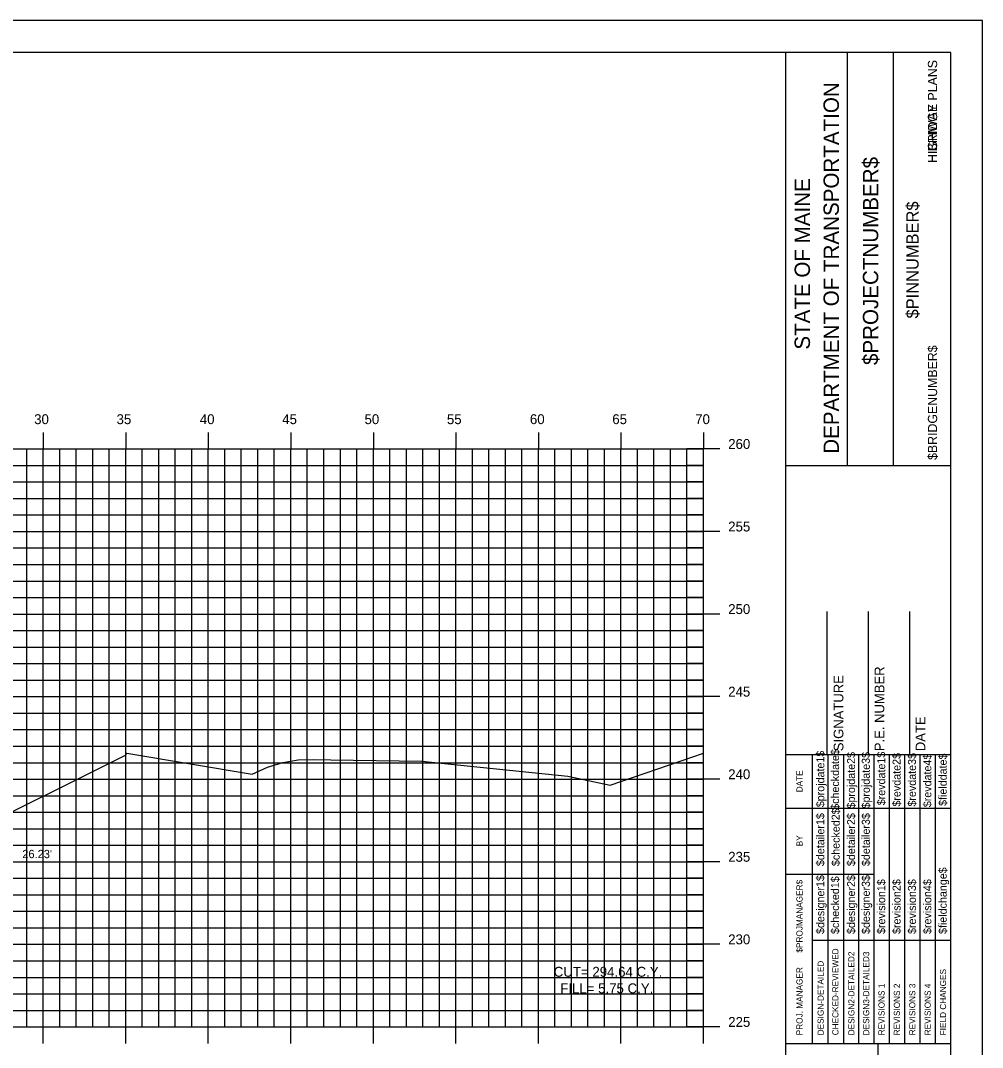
# Model space of a CAD drawing. Extents: x 1170543 to 1177585, y 609599 to 610623.
# Drawn here: x 1173611.6 to 1173669.9, y 609646.6 to 609708.8 of the extents above; entities that cross this region are included whole.
import ezdxf

# ---------------------------------------------------------------- set-up
doc = ezdxf.new("R2010")
doc.units = 0
for name, color, linetype in [('ANNOTATION', 7, 'Continuous'), ('BORDER', 7, 'Continuous'), ('BRIDGE_TITLE', 7, 'Continuous'), ('D_Roadway_Centerline_Text', 7, 'Continuous'), ('H_V ANNOTATION', 7, 'Continuous'), ('HIGHWAY_TITLE', 7, 'Continuous'), ('MAJOR', 7, 'Continuous'), ('MINOR', 7, 'Continuous'), ('PLOT BOUNDARY', 7, 'Continuous'), ('S_Roadway_Centerline', 7, 'Continuous')]:
    doc.layers.add(name, color=color, linetype=linetype)

msp = doc.modelspace()

# ---------------------------------------------------------------- linework, layer by layer
at = {"layer": 'BORDER'}
for p, q in [((1173668.017, 609706.872), (1173508.017, 609706.872)), ((1173658.017, 609601.875), (1173658.017, 609706.875)), ((1173661.746, 609681.869), (1173661.746, 609706.869)), ((1173664.541, 609681.869), (1173664.541, 609706.869)), ((1173668.017, 609601.875), (1173668.017, 609706.875)), ((1173658.018, 609681.866), (1173668.017, 609681.866)), ((1173660.517, 609664.375), (1173660.517, 609673.023)), ((1173663.017, 609664.375), (1173663.017, 609673.023)), ((1173665.517, 609664.375), (1173665.517, 609673.023)), ((1173658.017, 609664.375), (1173668.017, 609664.375)), ((1173658.017, 609646.875), (1173668.017, 609646.875)), ((1173663.608, 609611.875), (1173663.608, 609646.875))]:
    msp.add_line(p, q, dxfattribs=at)
for points in [[(1173659.632, 609661.125), (1173659.632, 609664.375)], [(1173660.565, 609646.878), (1173660.565, 609664.375)], [(1173661.497, 609664.375), (1173661.497, 609646.878)], [(1173662.428, 609646.878), (1173662.428, 609664.375)], [(1173663.36, 609646.878), (1173663.36, 609664.375)], [(1173664.292, 609646.878), (1173664.292, 609664.375)], [(1173665.223, 609646.878), (1173665.223, 609664.375)], [(1173666.155, 609646.878), (1173666.155, 609664.375)], [(1173667.087, 609646.878), (1173667.087, 609664.375)], [(1173659.633, 609646.878), (1173659.633, 609663.669)], [(1173658.017, 609661.125), (1173668.017, 609661.125)], [(1173658.017, 609657.125), (1173659.633, 609657.125)], [(1173659.632, 609657.125), (1173663.359, 609657.125)], [(1173659.632, 609653.125), (1173668.017, 609653.125)]]:
    msp.add_lwpolyline(points, dxfattribs=at)
at = {"layer": 'MAJOR'}
for p, q in [((1173613.017, 609683.874), (1173613.017, 609682.872)), ((1173618.017, 609683.874), (1173618.017, 609682.872)), ((1173623.017, 609683.874), (1173623.017, 609682.872)), ((1173628.017, 609683.874), (1173628.017, 609682.872)), ((1173633.017, 609683.874), (1173633.017, 609682.872)), ((1173638.017, 609683.874), (1173638.017, 609682.872)), ((1173643.017, 609683.874), (1173643.017, 609682.872)), ((1173648.017, 609683.874), (1173648.017, 609682.872)), ((1173653.017, 609683.874), (1173653.017, 609682.872)), ((1173513.017, 609682.872), (1173653.017, 609682.872)), ((1173513.017, 609682.872), (1173653.017, 609682.872)), ((1173613.017, 609647.872), (1173613.017, 609682.872)), ((1173618.017, 609647.872), (1173618.017, 609682.872)), ((1173623.017, 609647.872), (1173623.017, 609682.872)), ((1173628.017, 609647.872), (1173628.017, 609682.872)), ((1173633.017, 609647.872), (1173633.017, 609682.872)), ((1173638.017, 609647.872), (1173638.017, 609682.872)), ((1173643.017, 609647.872), (1173643.017, 609682.872)), ((1173648.017, 609647.872), (1173648.017, 609682.872)), ((1173654.019, 609682.872), (1173652.015, 609682.872)), ((1173653.017, 609647.872), (1173653.017, 609682.872)), ((1173653.017, 609647.872), (1173653.017, 609682.872)), ((1173513.017, 609677.872), (1173653.017, 609677.872)), ((1173654.019, 609677.872), (1173652.015, 609677.872)), ((1173513.017, 609672.872), (1173653.017, 609672.872)), ((1173654.019, 609672.872), (1173652.015, 609672.872)), ((1173513.017, 609667.872), (1173653.017, 609667.872)), ((1173654.019, 609667.872), (1173652.015, 609667.872)), ((1173513.017, 609662.872), (1173653.017, 609662.872)), ((1173654.019, 609662.872), (1173652.015, 609662.872)), ((1173513.017, 609657.872), (1173653.017, 609657.872)), ((1173654.019, 609657.872), (1173652.015, 609657.872)), ((1173513.017, 609652.872), (1173653.017, 609652.872)), ((1173654.019, 609652.872), (1173652.015, 609652.872)), ((1173513.017, 609647.872), (1173653.017, 609647.872)), ((1173513.017, 609647.872), (1173653.017, 609647.872)), ((1173613.017, 609646.87), (1173613.017, 609647.872)), ((1173618.017, 609646.87), (1173618.017, 609647.872)), ((1173623.017, 609646.87), (1173623.017, 609647.872)), ((1173628.017, 609646.87), (1173628.017, 609647.872)), ((1173633.017, 609646.87), (1173633.017, 609647.872)), ((1173638.017, 609646.87), (1173638.017, 609647.872)), ((1173643.017, 609646.87), (1173643.017, 609647.872)), ((1173648.017, 609646.87), (1173648.017, 609647.872)), ((1173654.019, 609647.872), (1173652.015, 609647.872)), ((1173653.017, 609646.87), (1173653.017, 609647.872))]:
    msp.add_line(p, q, dxfattribs=at)
at = {"layer": 'MINOR'}
for p, q in [((1173612.017, 609647.872), (1173612.017, 609682.872)), ((1173614.017, 609647.872), (1173614.017, 609682.872)), ((1173615.017, 609647.872), (1173615.017, 609682.872)), ((1173616.017, 609647.872), (1173616.017, 609682.872)), ((1173617.017, 609647.872), (1173617.017, 609682.872)), ((1173619.017, 609647.872), (1173619.017, 609682.872)), ((1173620.017, 609647.872), (1173620.017, 609682.872)), ((1173621.017, 609647.872), (1173621.017, 609682.872)), ((1173622.017, 609647.872), (1173622.017, 609682.872)), ((1173624.017, 609647.872), (1173624.017, 609682.872)), ((1173625.017, 609647.872), (1173625.017, 609682.872)), ((1173626.017, 609647.872), (1173626.017, 609682.872)), ((1173627.017, 609647.872), (1173627.017, 609682.872)), ((1173629.017, 609647.872), (1173629.017, 609682.872)), ((1173630.017, 609647.872), (1173630.017, 609682.872)), ((1173631.017, 609647.872), (1173631.017, 609682.872)), ((1173632.017, 609647.872), (1173632.017, 609682.872)), ((1173634.017, 609647.872), (1173634.017, 609682.872)), ((1173635.017, 609647.872), (1173635.017, 609682.872)), ((1173636.017, 609647.872), (1173636.017, 609682.872)), ((1173637.017, 609647.872), (1173637.017, 609682.872)), ((1173639.017, 609647.872), (1173639.017, 609682.872)), ((1173640.017, 609647.872), (1173640.017, 609682.872)), ((1173641.017, 609647.872), (1173641.017, 609682.872)), ((1173642.017, 609647.872), (1173642.017, 609682.872)), ((1173644.017, 609647.872), (1173644.017, 609682.872)), ((1173645.017, 609647.872), (1173645.017, 609682.872)), ((1173646.017, 609647.872), (1173646.017, 609682.872)), ((1173647.017, 609647.872), (1173647.017, 609682.872)), ((1173649.017, 609647.872), (1173649.017, 609682.872)), ((1173650.017, 609647.872), (1173650.017, 609682.872)), ((1173651.017, 609647.872), (1173651.017, 609682.872)), ((1173652.017, 609647.872), (1173652.017, 609682.872)), ((1173513.017, 609681.872), (1173653.017, 609681.872)), ((1173653.017, 609681.872), (1173652.015, 609681.872)), ((1173513.017, 609680.872), (1173653.017, 609680.872)), ((1173653.017, 609680.872), (1173652.015, 609680.872)), ((1173513.017, 609679.872), (1173653.017, 609679.872)), ((1173653.017, 609679.872), (1173652.015, 609679.872)), ((1173513.017, 609678.872), (1173653.017, 609678.872)), ((1173653.017, 609678.872), (1173652.015, 609678.872)), ((1173513.017, 609676.872), (1173653.017, 609676.872)), ((1173653.017, 609676.872), (1173652.015, 609676.872)), ((1173513.017, 609675.872), (1173653.017, 609675.872)), ((1173653.017, 609675.872), (1173652.015, 609675.872)), ((1173513.017, 609674.872), (1173653.017, 609674.872)), ((1173653.017, 609674.872), (1173652.015, 609674.872)), ((1173513.017, 609673.872), (1173653.017, 609673.872)), ((1173653.017, 609673.872), (1173652.015, 609673.872)), ((1173513.017, 609671.872), (1173653.017, 609671.872)), ((1173653.017, 609671.872), (1173652.015, 609671.872)), ((1173513.017, 609670.872), (1173653.017, 609670.872)), ((1173653.017, 609670.872), (1173652.015, 609670.872)), ((1173513.017, 609669.872), (1173653.017, 609669.872)), ((1173653.017, 609669.872), (1173652.015, 609669.872)), ((1173513.017, 609668.872), (1173653.017, 609668.872)), ((1173653.017, 609668.872), (1173652.015, 609668.872)), ((1173513.017, 609666.872), (1173653.017, 609666.872)), ((1173653.017, 609666.872), (1173652.015, 609666.872)), ((1173513.017, 609665.872), (1173653.017, 609665.872)), ((1173653.017, 609665.872), (1173652.015, 609665.872)), ((1173513.017, 609664.872), (1173653.017, 609664.872)), ((1173653.017, 609664.872), (1173652.015, 609664.872)), ((1173513.017, 609663.872), (1173653.017, 609663.872)), ((1173653.017, 609663.872), (1173652.015, 609663.872)), ((1173513.017, 609661.872), (1173653.017, 609661.872)), ((1173653.017, 609661.872), (1173652.015, 609661.872)), ((1173513.017, 609660.872), (1173653.017, 609660.872)), ((1173653.017, 609660.872), (1173652.015, 609660.872)), ((1173513.017, 609659.872), (1173653.017, 609659.872)), ((1173653.017, 609659.872), (1173652.015, 609659.872)), ((1173513.017, 609658.872), (1173653.017, 609658.872)), ((1173653.017, 609658.872), (1173652.015, 609658.872)), ((1173513.017, 609656.872), (1173653.017, 609656.872)), ((1173653.017, 609656.872), (1173652.015, 609656.872)), ((1173513.017, 609655.872), (1173653.017, 609655.872)), ((1173653.017, 609655.872), (1173652.015, 609655.872)), ((1173513.017, 609654.872), (1173653.017, 609654.872)), ((1173653.017, 609654.872), (1173652.015, 609654.872)), ((1173513.017, 609653.872), (1173653.017, 609653.872)), ((1173653.017, 609653.872), (1173652.015, 609653.872)), ((1173513.017, 609651.872), (1173653.017, 609651.872)), ((1173653.017, 609651.872), (1173652.015, 609651.872)), ((1173513.017, 609650.872), (1173653.017, 609650.872)), ((1173653.017, 609650.872), (1173652.015, 609650.872)), ((1173513.017, 609649.872), (1173653.017, 609649.872)), ((1173653.017, 609649.872), (1173652.015, 609649.872)), ((1173513.017, 609648.872), (1173653.017, 609648.872)), ((1173653.017, 609648.872), (1173652.015, 609648.872))]:
    msp.add_line(p, q, dxfattribs=at)
at = {"layer": 'PLOT BOUNDARY'}
msp.add_lwpolyline([(1173499.924, 609598.813), (1173669.924, 609598.813), (1173669.924, 609708.813), (1173499.924, 609708.813)], close=True, dxfattribs=at)
at = {"layer": 'S_Roadway_Centerline'}
msp.add_lwpolyline([(1173608.191, 609659.447), (1173617.969, 609664.31), (1173618.032, 609664.341), (1173618.033, 609664.453), (1173618.034, 609664.452), (1173618.082, 609664.451), (1173625.682, 609663.18), (1173626.612, 609663.59), (1173627.539, 609663.874), (1173628.463, 609664.034), (1173629.385, 609664.068), (1173630.437, 609664.048), (1173635.959, 609663.97), (1173644.807, 609663.058), (1173647.356, 609662.504), (1173653.017, 609664.454)], dxfattribs=at)

# ---------------------------------------------------------------- texts
at = {"layer": 'ANNOTATION'}
msp.add_text("26.23'", height=0.5, dxfattribs=at).set_placement((1173611.748, 609658.09))
at = {"layer": 'BORDER'}
for s, height, p in [('DEPARTMENT OF TRANSPORTATION', 0.93176, (1173661.224, 609682.578)), ('$PROJECTNUMBER$', 0.93176, (1173663.609, 609687.951)), ('STATE OF MAINE', 0.93176, (1173659.473, 609688.884)), ('$PINNUMBER$', 0.74527, (1173666.054, 609690.769)), ('P.E. NUMBER', 0.59055, (1173663.978, 609664.567)), ('SIGNATURE', 0.5906, (1173661.498, 609664.567)), ('DATE', 0.5906, (1173666.459, 609664.567)), ('$checkdate$', 0.48455, (1173661.235, 609661.018)), ('$projdate1$', 0.48455, (1173660.34, 609661.176)), ('$projdate2$', 0.48455, (1173662.204, 609661.097)), ('$projdate3$', 0.48455, (1173663.098, 609661.097)), ('$revdate1$', 0.4845, (1173664.03, 609661.294)), ('$revdate2$', 0.4845, (1173664.962, 609661.215)), ('$revdate3$', 0.4845, (1173665.893, 609661.215)), ('$revdate4$', 0.4845, (1173666.825, 609661.176)), ('$fielddate$', 0.48455, (1173667.757, 609661.254)), ('DATE', 0.3714, (1173659.022, 609662.081)), ('$checked2$', 0.4845, (1173661.272, 609657.61)), ('$detailer1$', 0.48455, (1173660.34, 609657.61)), ('$detailer2$', 0.48455, (1173662.204, 609657.61)), ('$detailer3$', 0.48455, (1173663.098, 609657.61)), ('BY', 0.3714, (1173659.022, 609658.81)), ('$fieldchange$', 0.48455, (1173667.757, 609653.498)), ('$PROJMANAGER$', 0.37275, (1173659.022, 609652.37)), ('$designer1$', 0.48455, (1173660.34, 609653.498)), ('$checked1$', 0.4845, (1173661.235, 609653.498)), ('$designer2$', 0.48455, (1173662.204, 609653.498)), ('$designer3$', 0.48455, (1173663.098, 609653.498)), ('$revision1$', 0.48455, (1173664.03, 609653.498)), ('$revision2$', 0.48455, (1173664.962, 609653.498)), ('$revision3$', 0.48455, (1173665.893, 609653.498)), ('$revision4$', 0.48455, (1173666.825, 609653.498)), ('CHECKED-REVIEWED', 0.37275, (1173661.198, 609647.363)), ('DESIGN2-DETAILED2', 0.37275, (1173662.167, 609647.363)), ('DESIGN3-DETAILED3', 0.37275, (1173663.062, 609647.363)), ('DESIGN-DETAILED', 0.37275, (1173660.304, 609647.363)), ('PROJ. MANAGER', 0.37275, (1173659.022, 609647.363)), ('FIELD CHANGES', 0.37275, (1173667.72, 609647.363)), ('REVISIONS 1', 0.37275, (1173663.993, 609647.363)), ('REVISIONS 2', 0.37275, (1173664.925, 609647.363)), ('REVISIONS 3', 0.37275, (1173665.857, 609647.363)), ('REVISIONS 4', 0.37275, (1173666.789, 609647.363))]:
    msp.add_text(s, height=height, rotation=90, dxfattribs=at).set_placement(p)
at = {"layer": 'BRIDGE_TITLE'}
for s, p in [('BRIDGE PLANS', (1173667.176, 609700.897)), ('$BRIDGENUMBER$', (1173667.176, 609682.203))]:
    msp.add_text(s, height=0.55901, rotation=90, dxfattribs=at).set_placement(p)
at = {"layer": 'D_Roadway_Centerline_Text'}
for s, p in [('CUT= 294.64 C.Y.', (1173643.948, 609650.908)), ('FILL= 5.75 C.Y.', (1173644.339, 609649.906))]:
    msp.add_text(s, height=0.6, dxfattribs=at).set_placement(p)
at = {"layer": 'H_V ANNOTATION'}
for s, p in [('30', (1173612.466, 609684.372)), ('35', (1173617.458, 609684.372)), ('40', (1173622.503, 609684.372)), ('45', (1173627.495, 609684.372)), ('50', (1173632.482, 609684.372)), ('55', (1173637.474, 609684.372)), ('60', (1173642.503, 609684.372)), ('65', (1173647.495, 609684.372)), ('70', (1173652.519, 609684.372)), ('260', (1173654.517, 609682.872)), ('255', (1173654.517, 609677.872)), ('250', (1173654.517, 609672.872)), ('245', (1173654.517, 609667.872)), ('240', (1173654.517, 609662.872)), ('235', (1173654.517, 609657.872)), ('230', (1173654.517, 609652.872)), ('225', (1173654.517, 609647.872))]:
    msp.add_text(s, height=0.6, dxfattribs=at).set_placement(p)
at = {"layer": 'HIGHWAY_TITLE'}
msp.add_text('HIGHWAY PLANS', height=0.55901, rotation=90, dxfattribs=at).set_placement((1173667.176, 609700.188))

doc.saveas('drawing.dxf')
